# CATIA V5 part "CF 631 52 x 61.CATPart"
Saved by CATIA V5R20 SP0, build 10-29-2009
Part number: CF 631 52 x 61
Definition: NONE
Nomenclature: CF 631 52 x 61
Source: Unknown
Description: CF 631 52 x 61
Bounding box of the stored display mesh (mm): x -13 to 48, y -39.5 to 39.5, z -39.5 to 39.5
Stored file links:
  C:\Users\Utente\Desktop\IO LAVORO\3D X SITO CF\X SITO\CF 631\CF 631 52 x 61.CATPart
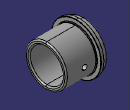
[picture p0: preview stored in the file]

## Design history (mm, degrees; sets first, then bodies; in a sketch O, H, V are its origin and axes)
Body1 "CF 631 52 x 61" (main body)
  Solid1: solid without history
